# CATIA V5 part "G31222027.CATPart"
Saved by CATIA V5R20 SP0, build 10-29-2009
Part number: G31222027
Revision: 9
Definition: design
Nomenclature: G31222027
Source: made
Description: NOT SPECIFIED
Bounding box of the stored display mesh (mm): x -8 to 27, y -17.322 to 17.322, z -17.5 to 17.5
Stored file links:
  C:\Users\Raffaele\Desktop\3D X SITO CF\BOLEX\23-BUSH REF 312\G31222027.CATPart

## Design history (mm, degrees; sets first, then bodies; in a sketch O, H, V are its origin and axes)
Body1 "MANIFOLD_SOLID_BREP #6083" (main body)
  Solid1: solid without history
Body2 "MANIFOLD_SOLID_BREP #6230"
  Solid2: solid without history
Body3 "MANIFOLD_SOLID_BREP #6377"
  Solid3: solid without history
Body4 "MANIFOLD_SOLID_BREP #6524"
  Solid4: solid without history
Body5 "MANIFOLD_SOLID_BREP #6671"
  Solid5: solid without history
Body6 "MANIFOLD_SOLID_BREP #6820"
  Solid6: solid without history
Body7 "MANIFOLD_SOLID_BREP #6969"
  Solid7: solid without history
Body8 "MANIFOLD_SOLID_BREP #7118"
  Solid8: solid without history
Body9 "MANIFOLD_SOLID_BREP #7267"
  Solid9: solid without history
Body10 "MANIFOLD_SOLID_BREP #7416"
  Solid10: solid without history
Body11 "MANIFOLD_SOLID_BREP #7565"
  Solid11: solid without history
Body12 "MANIFOLD_SOLID_BREP #7714"
  Solid12: solid without history
Body13 "MANIFOLD_SOLID_BREP #7863"
  Solid13: solid without history
Body14 "MANIFOLD_SOLID_BREP #8012"
  Solid14: solid without history
Body15 "MANIFOLD_SOLID_BREP #8161"
  Solid15: solid without history
Body16 "MANIFOLD_SOLID_BREP #8310"
  Solid16: solid without history
Body17 "MANIFOLD_SOLID_BREP #8459"
  Solid17: solid without history
Body18 "MANIFOLD_SOLID_BREP #8608"
  Solid18: solid without history
Body19 "MANIFOLD_SOLID_BREP #8757"
  Solid19: solid without history
Body20 "MANIFOLD_SOLID_BREP #8906"
  Solid20: solid without history
Body21 "MANIFOLD_SOLID_BREP #9055"
  Solid21: solid without history
Body22 "MANIFOLD_SOLID_BREP #9204"
  Solid22: solid without history
Body23 "MANIFOLD_SOLID_BREP #9353"
  Solid23: solid without history
Body24 "MANIFOLD_SOLID_BREP #9502"
  Solid24: solid without history
Body25 "MANIFOLD_SOLID_BREP #9651"
  Solid25: solid without history
Body26 "MANIFOLD_SOLID_BREP #9800"
  Solid26: solid without history
Body27 "MANIFOLD_SOLID_BREP #9949"
  Solid27: solid without history
Body28 "MANIFOLD_SOLID_BREP #10098"
  Solid28: solid without history
Body29 "MANIFOLD_SOLID_BREP #10247"
  Solid29: solid without history
Body30 "MANIFOLD_SOLID_BREP #10396"
  Solid30: solid without history
Body31 "MANIFOLD_SOLID_BREP #10545"
  Solid31: solid without history
Body32 "MANIFOLD_SOLID_BREP #10692"
  Solid32: solid without history
Body33 "MANIFOLD_SOLID_BREP #10839"
  Solid33: solid without history
Body34 "MANIFOLD_SOLID_BREP #10988"
  Solid34: solid without history
Body35 "MANIFOLD_SOLID_BREP #11137"
  Solid35: solid without history
Body36 "MANIFOLD_SOLID_BREP #11286"
  Solid36: solid without history
Body37 "MANIFOLD_SOLID_BREP #11435"
  Solid37: solid without history
Body38 "MANIFOLD_SOLID_BREP #11584"
  Solid38: solid without history
Body39 "MANIFOLD_SOLID_BREP #11733"
  Solid39: solid without history
Body40 "MANIFOLD_SOLID_BREP #11882"
  Solid40: solid without history
Body41 "MANIFOLD_SOLID_BREP #12031"
  Solid41: solid without history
